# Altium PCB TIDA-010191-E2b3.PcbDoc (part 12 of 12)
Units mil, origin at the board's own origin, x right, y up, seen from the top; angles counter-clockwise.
Board outline 9842.52 x 9842.4 mil, 6 copper layers (Layer 1 - Top Layer, Layer 2 - GND Layer, Layer 3 - Signal, Layer 4 - Signal, Layer 5 - GND, Bottom Layer), stack 59.9 mil thick; 1178 components, 642 nets, 3329 pads, 2967 vias.
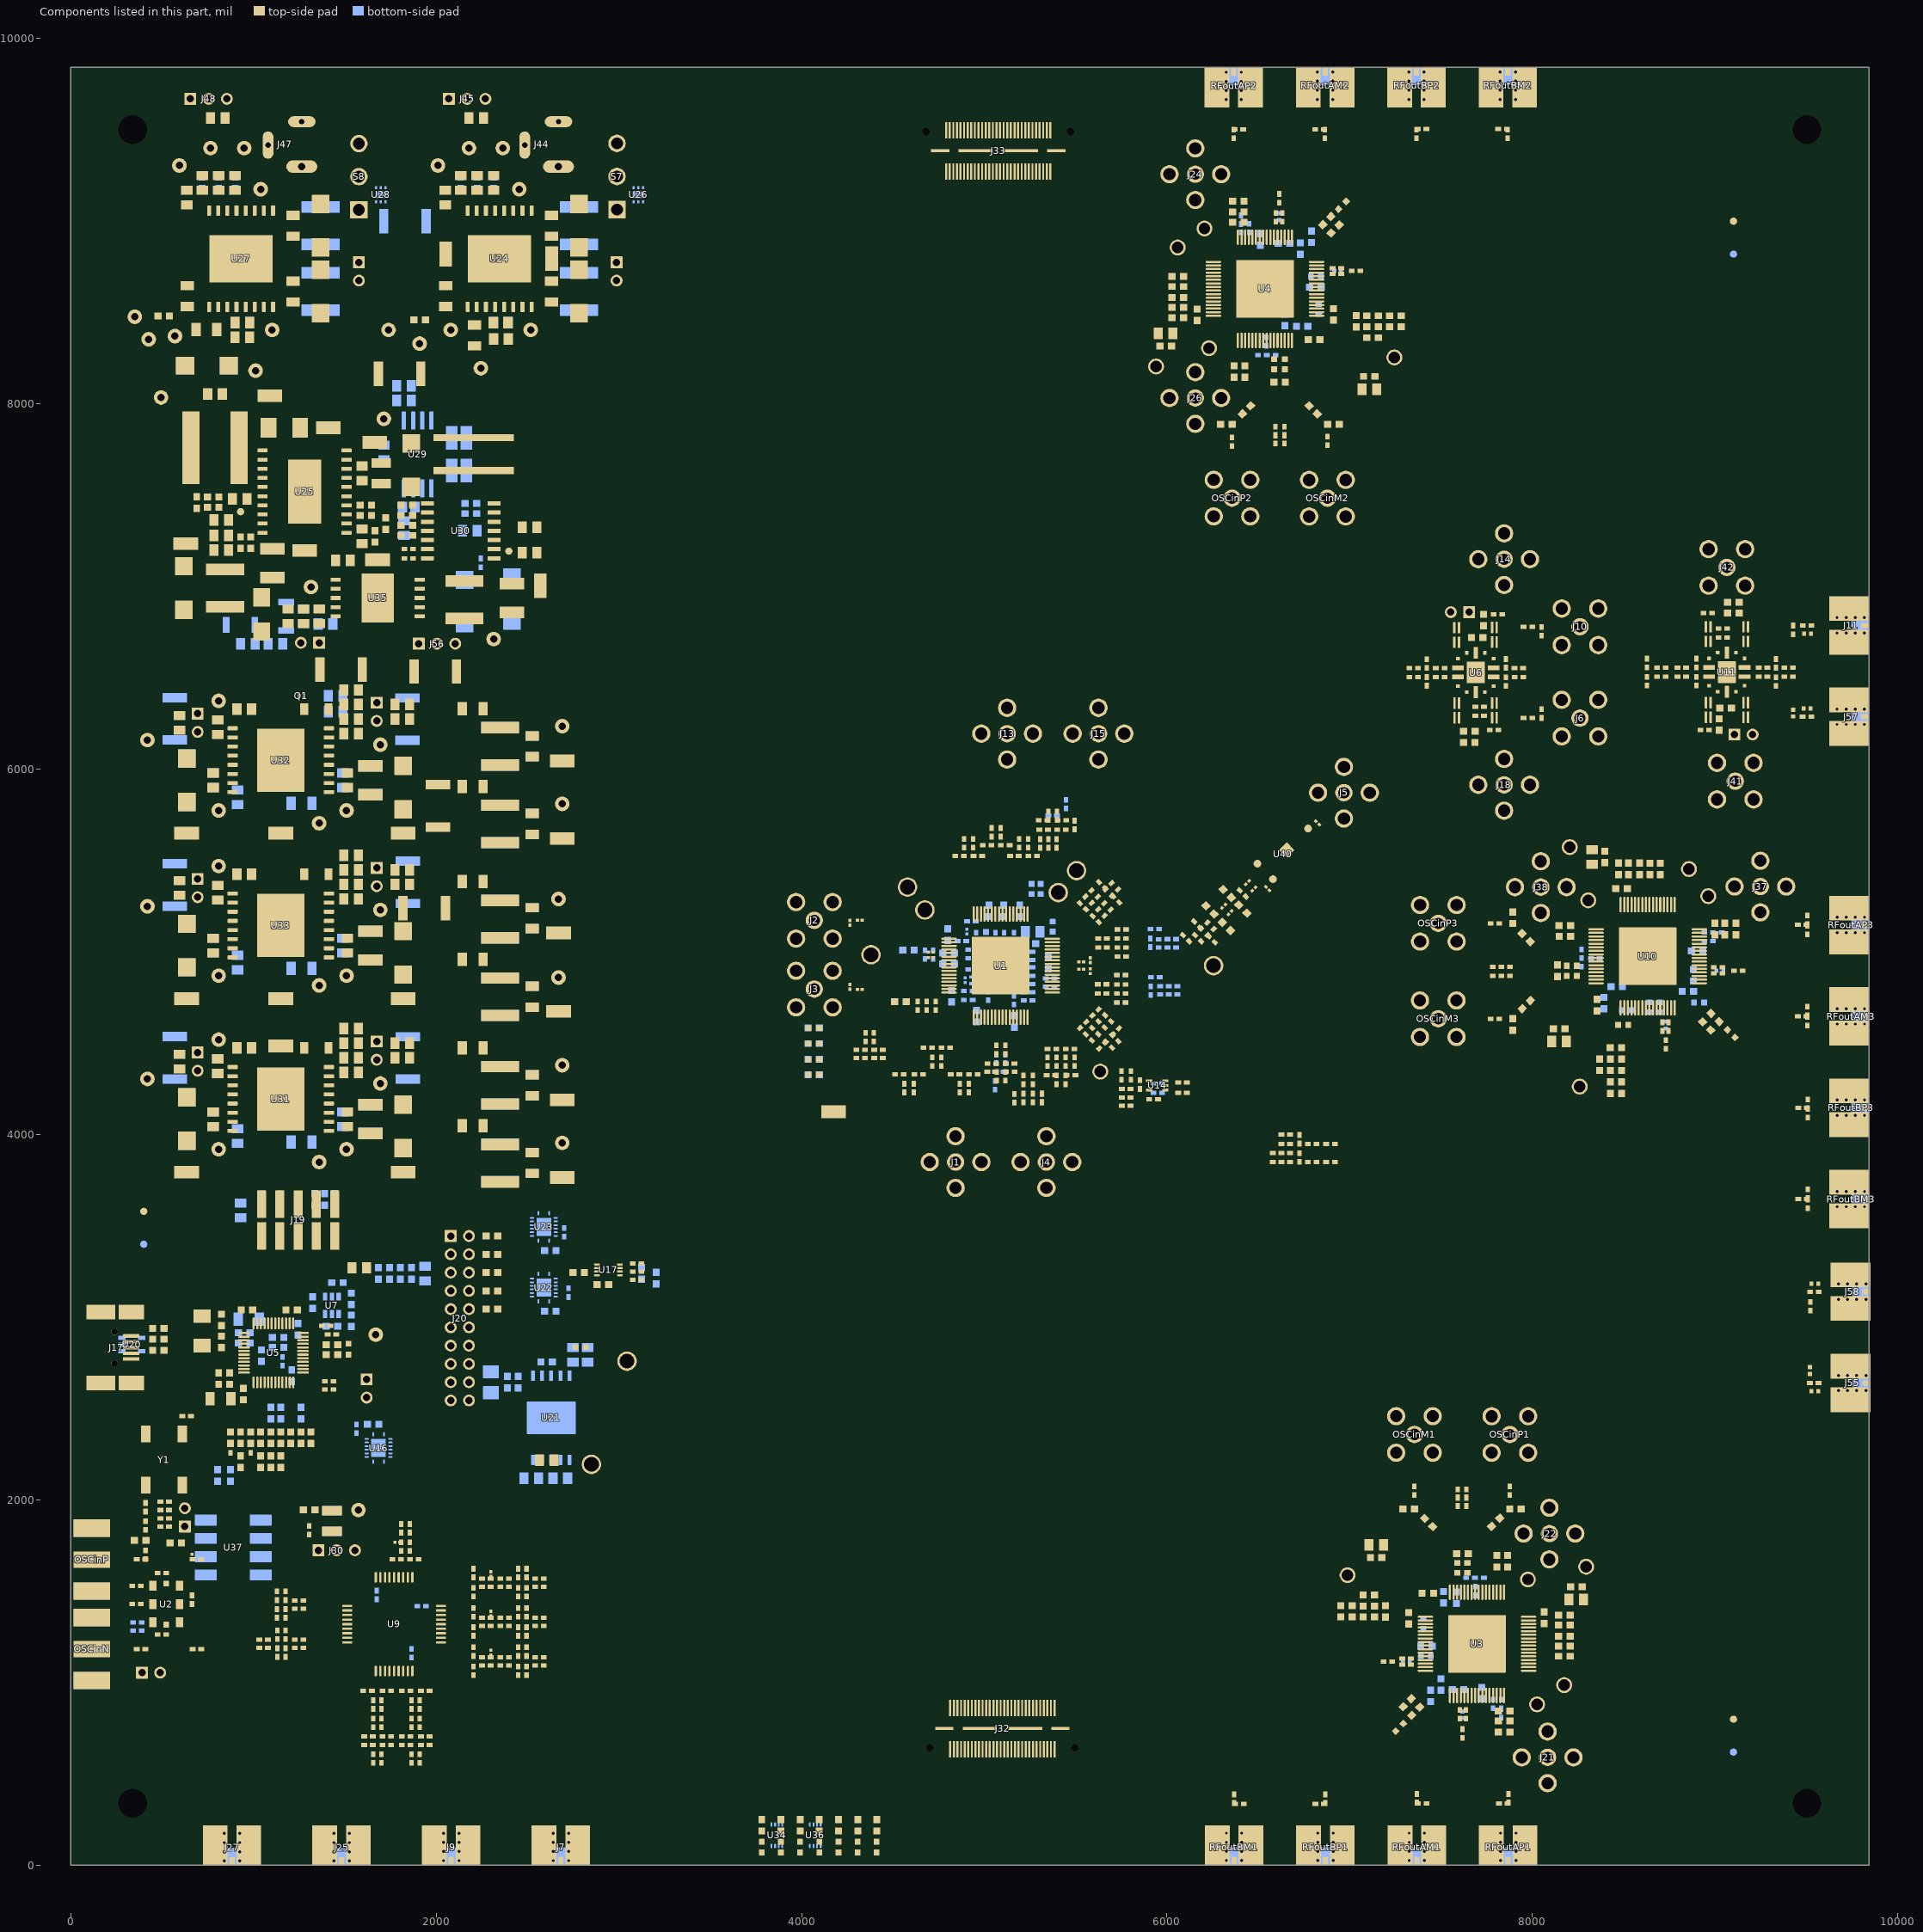
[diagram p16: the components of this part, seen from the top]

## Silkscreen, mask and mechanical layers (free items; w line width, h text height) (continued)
Drill Drawing:
  circle w10: c15910.96,11053.45 r20
  circle w10: c15910.96,11053.45 r33.33
  circle w10: c15910.96,10303.45 r33.33
  lines w10: 15877.63,9970.12 15944.3,9970.12 15944.3,10036.78 15877.63,10036.78 15877.63,9970.12 ; 15877.63,10120.12 15877.63,10136.78 15894.3,10153.45 15877.63,10170.12 15877.63,10186.78 15894.3,10186.78 15910.96,10170.12 15927.63,10186.78 15944.3,10186.78 15944.3,10170.12 15927.63,10153.45 15944.3,10136.78 15944.3,10120.12 15927.63,10120.12 15910.96,10136.78 15894.3,10120.12 15877.63,10120.12 ; 15877.63,10603.45 15910.96,10570.12 15944.3,10603.45 15910.96,10636.78 15877.63,10603.45 ; 15877.63,10720.12 15944.3,10720.12 15944.3,10786.78 15877.63,10786.78 15877.63,10720.12 ; 15877.63,10886.78 15894.3,10886.78 15894.3,10870.12 15927.63,10870.12 15927.63,10886.78 15944.3,10886.78 15944.3,10920.12 15927.63,10920.12 15927.63,10936.78 15894.3,10936.78 15894.3,10920.12 15877.63,10920.12 15877.63,10886.78 ; 15877.63,11186.78 15894.3,11186.78 15910.96,11170.12 15927.63,11186.78 15944.3,11186.78 15927.63,11203.45 15944.3,11220.12 15927.63,11220.12 15910.96,11236.78 15894.3,11220.12 15877.63,11220.12 15894.3,11203.45 15877.63,11186.78 ; 15877.63,11386.78 15944.3,11386.78 15910.96,11320.12 15877.63,11386.78 ; 15877.63,11486.78 15894.3,11486.78 15910.96,11470.12 15927.63,11486.78 15944.3,11486.78 15927.63,11503.45 15944.3,11520.12 15927.63,11520.12 15910.96,11536.78 15894.3,11520.12 15877.63,11520.12 15894.3,11503.45 15877.63,11486.78 ; 15877.63,11836.78 15944.3,11836.78 15910.96,11770.12 15877.63,11836.78 ; 15877.63,11920.12 15910.96,11936.78 15944.3,11920.12 15927.63,11953.45 15944.3,11986.78 15910.96,11970.12 15877.63,11986.78 15894.3,11953.45 15877.63,11920.12 ; 15890.96,9983.45 15930.96,9983.45 15930.96,10023.45 15890.96,10023.45 15890.96,9983.45 ; 15890.96,11373.45 15930.96,11373.45 15910.96,11333.45 15890.96,11373.45 ; 15890.96,11493.45 15900.96,11493.45 15910.96,11483.45 15920.96,11493.45 15930.96,11493.45 15920.96,11503.45 15930.96,11513.45 15920.96,11513.45 15910.96,11523.45 15900.96,11513.45 15890.96,11513.45 15900.96,11503.45 15890.96,11493.45 ; 15890.96,11933.45 15910.96,11943.45 15930.96,11933.45 15920.96,11953.45 15930.96,11973.45 15910.96,11963.45 15890.96,11973.45 15900.96,11953.45 15890.96,11933.45
  lines w15: 15817.84,9925.12 21152.41,9925.12 ; 15817.84,12175.12 21152.41,12175.12 ; 16368.71,9775.12 16368.71,12325.12 ; 17028.54,9775.12 17028.54,12325.12 ; 18128.22,9775.12 18128.22,12325.12 ; 18634.09,9775.12 18634.09,12325.12 ; 19367.89,9775.12 19367.89,12325.12 ; 19957.74,9775.12 19957.74,12325.12 ; 15817.84,9775.12 21152.41,9775.12 21152.41,12325.12 15817.84,12325.12 15817.84,9775.12
  text "Symbol" at 15907.84,12220.12 h72
  text "Count" at 16413.71,12220.12 h72
  text "Hole Size" at 17073.54,12220.12 h72
  text "Plated" at 18173.22,12220.12 h72
  text "Hole Type" at 18679.09,12220.12 h72
  text "Via/Pad" at 19412.89,12220.12 h72
  text "Hole Length" at 20002.74,12220.12 h72
  text "338" at 16413.71,12070.12 h60
  text "7.87mil (0.200mm)" at 17073.54,12070.12 h60
  text "PTH" at 18173.22,12070.12 h60
  text "Round" at 18679.09,12070.12 h60
  text "Via" at 19412.89,12070.12 h60
  text "-" at 20002.74,12070.12 h60
  text "I" at 15889.86,12060.13 h66.67
  text "2755" at 16413.71,11920.12 h60
  text "10.00mil (0.254mm)" at 17073.54,11920.12 h60
  text "PTH" at 18173.22,11920.12 h60
  text "Round" at 18679.09,11920.12 h60
  text "Via" at 19412.89,11920.12 h60
  text "-" at 20002.74,11920.12 h60
  text "4" at 16413.71,11770.12 h60
  text "12.00mil (0.305mm)" at 17073.54,11770.12 h60
  text "PTH" at 18173.22,11770.12 h60
  text "Round" at 18679.09,11770.12 h60
  text "Via" at 19412.89,11770.12 h60
  text "-" at 20002.74,11770.12 h60
  text "160" at 16413.71,11620.12 h60
  text "16.00mil (0.406mm)" at 17073.54,11620.12 h60
  text "PTH" at 18173.22,11620.12 h60
  text "Round" at 18679.09,11620.12 h60
  text "Pad" at 19412.89,11620.12 h60
  text "-" at 20002.74,11620.12 h60
  text "F" at 15878.75,11610.13 h66.67
  text "8" at 16413.71,11470.12 h60
  text "25.00mil (0.635mm)" at 17073.54,11470.12 h60
  text "PTH" at 18173.22,11470.12 h60
  text "Round" at 18679.09,11470.12 h60
  text "Via" at 19412.89,11470.12 h60
  text "-" at 20002.74,11470.12 h60
  text "4" at 16413.71,11320.12 h60
  text "29.92mil (0.760mm)" at 17073.54,11320.12 h60
  text "PTH" at 18173.22,11320.12 h60
  text "Slot" at 18679.09,11320.12 h60
  text "Pad" at 19412.89,11320.12 h60
  text "120.08mil (3.050mm)" at 20002.74,11320.12 h60
  text "2" at 16413.71,11170.12 h60
  text "35.43mil (0.900mm)" at 17073.54,11170.12 h60
  text "NPTH" at 18173.22,11170.12 h60
  text "Round" at 18679.09,11170.12 h60
  text "Pad" at 19412.89,11170.12 h60
  text "-" at 20002.74,11170.12 h60
  text "2" at 16413.71,11020.12 h60
  text "39.76mil (1.010mm)" at 17073.54,11020.12 h60
  text "PTH" at 18173.22,11020.12 h60
  text "Slot" at 18679.09,11020.12 h60
  text "Pad" at 19412.89,11020.12 h60
  text "140.16mil (3.560mm)" at 20002.74,11020.12 h60
  text "111" at 16413.71,10870.12 h60
  text "40.00mil (1.016mm)" at 17073.54,10870.12 h60
  text "PTH" at 18173.22,10870.12 h60
  text "Round" at 18679.09,10870.12 h60
  text "Pad" at 19412.89,10870.12 h60
  text "-" at 20002.74,10870.12 h60
  text "4" at 16413.71,10720.12 h60
  text "40.16mil (1.020mm)" at 17073.54,10720.12 h60
  text "NPTH" at 18173.22,10720.12 h60
  text "Round" at 18679.09,10720.12 h60
  text "Pad" at 19412.89,10720.12 h60
  text "-" at 20002.74,10720.12 h60
  text "25" at 16413.71,10570.12 h60
  text "62.00mil (1.575mm)" at 17073.54,10570.12 h60
  text "PTH" at 18173.22,10570.12 h60
  text "Round" at 18679.09,10570.12 h60
  text "Pad" at 19412.89,10570.12 h60
  text "-" at 20002.74,10570.12 h60
  text "16" at 16413.71,10420.12 h60
  text "63.00mil (1.600mm)" at 17073.54,10420.12 h60
  text "PTH" at 18173.22,10420.12 h60
  text "Round" at 18679.09,10420.12 h60
  text "Pad" at 19412.89,10420.12 h60
  text "-" at 20002.74,10420.12 h60
  text "J" at 15878.75,10410.13 h66.67
  text "6" at 16413.71,10270.12 h60
  text "64.96mil (1.650mm)" at 17073.54,10270.12 h60
  text "PTH" at 18173.22,10270.12 h60
  text "Round" at 18679.09,10270.12 h60
  text "Pad" at 19412.89,10270.12 h60
  text "-" at 20002.74,10270.12 h60
  text "100" at 16413.71,10120.12 h60
  text "67.00mil (1.702mm)" at 17073.54,10120.12 h60
  text "PTH" at 18173.22,10120.12 h60
  text "Round" at 18679.09,10120.12 h60
  text "Pad" at 19412.89,10120.12 h60
  text "-" at 20002.74,10120.12 h60
  text "8" at 16413.71,9970.12 h60
  text "80.71mil (2.050mm)" at 17073.54,9970.12 h60
  text "PTH" at 18173.22,9970.12 h60
  text "Round" at 18679.09,9970.12 h60
  text "Pad" at 19412.89,9970.12 h60
  text "-" at 20002.74,9970.12 h60
  text "3543 Total" at 16413.71,9820.12 h60
  text "Slot definitions :" at 15907.84,9675.14 h60
  text "Routed Path Length" at 16940.53,9675.14 h60
  text "= Calculated from tool start centre position to tool end centre position." at 18043.19,9675.14 h60
  text "Hole Length" at 16940.53,9575.17 h60
  text "= Routed Path Length + Tool Size = Slot length as defined in the PCB layout" at 17633.33,9575.17 h60
  text "Drill Table" at 10625.95,8566.12 h60
  text "FOR 7.874MIL DRILL +0/-7.874MIL" at 10593.38,8435.72 h60
  text "FOR 10MIL DRILL +0/-10MIL" at 10588.38,8335.72 h60
  text "FOR 12MIL DRILL +0/-12MIL" at 10588.38,8240.72 h60
  text "FOR 16MIL DRILL +0/-16MIL" at 10588.38,8141.46 h60
  text "FOR PTH DRILL +/-3MIL" at 10590.94,8023.12 h60
  text "FOR NPTH DRILL +/-2MIL" at 10590.94,7943.12 h60
  text "DRILL DRAWING" at -231.28,-1903.37 h60

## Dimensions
0.09,0.12 to 9842.61,0.12 on M2 Board Dimensions
0.09,0.12 to 0.09,9842.52 on M2 Board Dimensions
